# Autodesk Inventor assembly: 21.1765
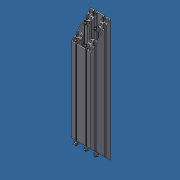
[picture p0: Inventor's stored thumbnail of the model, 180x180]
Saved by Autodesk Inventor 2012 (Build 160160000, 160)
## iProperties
Created: 2007-07
Part Number: 21.1765
Document SubType Name: Assembly
Designer: Andy Moles
Description: STRENGTHENING ELEMENT 90
Mass: 2691.83 g
Surface Area: 5939.89 cm^2
Volume: 949.886 cm^3
Density: 2.83385 g/cm^3
Author: Andy Moles
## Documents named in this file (4)
- C:\Andys Backup Data\ANDY'S INVENTOR\INVENTOR LIBRARIES\PARTS LIBRARY\FEET WHEELS FLOOR FASTENING SUPPORTS\21.1765 STRENGTHENING ELEMENT 90x90.iam
- C:\Andys Backup Data\ANDY'S INVENTOR\INVENTOR LIBRARIES\PARTS LIBRARY\FEET WHEELS FLOOR FASTENING SUPPORTS\SUBCOMPONENTS\21.1765_1 STRENGTHENING ELEMENT 90x90.ipt
- C:\Andys Backup Data\ANDY'S INVENTOR\INVENTOR LIBRARIES\PARTS LIBRARY\FASTENING ELEMENTS\SCREWS CAP\21.1208 M8X35.ipt
- C:\Andys Backup Data\ANDY'S INVENTOR\INVENTOR LIBRARIES\PARTS LIBRARY\FASTENING ELEMENTS\NUTS\21.1351_2 M8 SQUARE NUT POS FXG.ipt
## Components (17 placed, 3 different names)
1. 21.1765_1 STRENGTHENING ELEMENT 90x90:1 — Insert:1, Insert:2, Insert:3, Insert:4, Insert:5, Insert:6, Insert:7, Insert:8, Mate:1, Mate:2, Mate:3, Mate:4, Mate:9, Mate:10, Mate:11, Mate:12
2. 21.1208  M8 x 35:1 — Insert:1, Mate:6
3. 21.1208  M8 x 35:2 — Insert:4, Mate:7
4. 21.1208  M8 x 35:3 — Insert:3, Mate:8
5. 21.1208  M8 x 35:4 — Insert:2, Mate:5
6. 21.1208  M8 x 35:5 — Insert:7, Mate:15
7. 21.1208  M8 x 35:6 — Insert:8, Mate:16
8. 21.1208  M8 x 35:7 — Insert:6, Mate:13
9. 21.1208  M8 x 35:8 — Insert:5, Mate:14
10. 21.1351_2 M8 SQUARE NUT POS FXG:1 — Mate:1, Mate:6
11. 21.1351_2 M8 SQUARE NUT POS FXG:2 — Mate:2, Mate:7
12. 21.1351_2 M8 SQUARE NUT POS FXG:3 — Mate:3, Mate:8
13. 21.1351_2 M8 SQUARE NUT POS FXG:4 — Mate:4, Mate:5
14. 21.1351_2 M8 SQUARE NUT POS FXG:5 — Mate:9, Mate:15
15. 21.1351_2 M8 SQUARE NUT POS FXG:6 — Mate:12, Mate:13
16. 21.1351_2 M8 SQUARE NUT POS FXG:7 — Mate:11, Mate:14
17. 21.1351_2 M8 SQUARE NUT POS FXG:8 — Mate:10, Mate:16
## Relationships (24: Mate 16, Insert 8)
- Insert:1: 21.1765_1 STRENGTHENING ELEMENT 90x90:1 ↔ 21.1208  M8 x 35:1
- Insert:2: 21.1765_1 STRENGTHENING ELEMENT 90x90:1 ↔ 21.1208  M8 x 35:4
- Insert:3: 21.1765_1 STRENGTHENING ELEMENT 90x90:1 ↔ 21.1208  M8 x 35:3
- Insert:4: 21.1765_1 STRENGTHENING ELEMENT 90x90:1 ↔ 21.1208  M8 x 35:2
- Insert:5: 21.1765_1 STRENGTHENING ELEMENT 90x90:1 ↔ 21.1208  M8 x 35:8
- Insert:6: 21.1765_1 STRENGTHENING ELEMENT 90x90:1 ↔ 21.1208  M8 x 35:7
- Insert:7: 21.1765_1 STRENGTHENING ELEMENT 90x90:1 ↔ 21.1208  M8 x 35:5
- Insert:8: 21.1765_1 STRENGTHENING ELEMENT 90x90:1 ↔ 21.1208  M8 x 35:6
- Mate:1: 21.1765_1 STRENGTHENING ELEMENT 90x90:1 ↔ 21.1351_2 M8 SQUARE NUT POS FXG:1
- Mate:2: 21.1765_1 STRENGTHENING ELEMENT 90x90:1 ↔ 21.1351_2 M8 SQUARE NUT POS FXG:2
- Mate:3: 21.1765_1 STRENGTHENING ELEMENT 90x90:1 ↔ 21.1351_2 M8 SQUARE NUT POS FXG:3
- Mate:4: 21.1765_1 STRENGTHENING ELEMENT 90x90:1 ↔ 21.1351_2 M8 SQUARE NUT POS FXG:4
- Mate:5: 21.1208  M8 x 35:4 ↔ 21.1351_2 M8 SQUARE NUT POS FXG:4
- Mate:6: 21.1208  M8 x 35:1 ↔ 21.1351_2 M8 SQUARE NUT POS FXG:1
- Mate:7: 21.1208  M8 x 35:2 ↔ 21.1351_2 M8 SQUARE NUT POS FXG:2
- Mate:8: 21.1208  M8 x 35:3 ↔ 21.1351_2 M8 SQUARE NUT POS FXG:3
- Mate:9: 21.1765_1 STRENGTHENING ELEMENT 90x90:1 ↔ 21.1351_2 M8 SQUARE NUT POS FXG:5
- Mate:10: 21.1765_1 STRENGTHENING ELEMENT 90x90:1 ↔ 21.1351_2 M8 SQUARE NUT POS FXG:8
- Mate:11: 21.1765_1 STRENGTHENING ELEMENT 90x90:1 ↔ 21.1351_2 M8 SQUARE NUT POS FXG:7
- Mate:12: 21.1765_1 STRENGTHENING ELEMENT 90x90:1 ↔ 21.1351_2 M8 SQUARE NUT POS FXG:6
- Mate:13: 21.1208  M8 x 35:7 ↔ 21.1351_2 M8 SQUARE NUT POS FXG:6
- Mate:14: 21.1208  M8 x 35:8 ↔ 21.1351_2 M8 SQUARE NUT POS FXG:7
- Mate:15: 21.1208  M8 x 35:5 ↔ 21.1351_2 M8 SQUARE NUT POS FXG:5
- Mate:16: 21.1208  M8 x 35:6 ↔ 21.1351_2 M8 SQUARE NUT POS FXG:8
